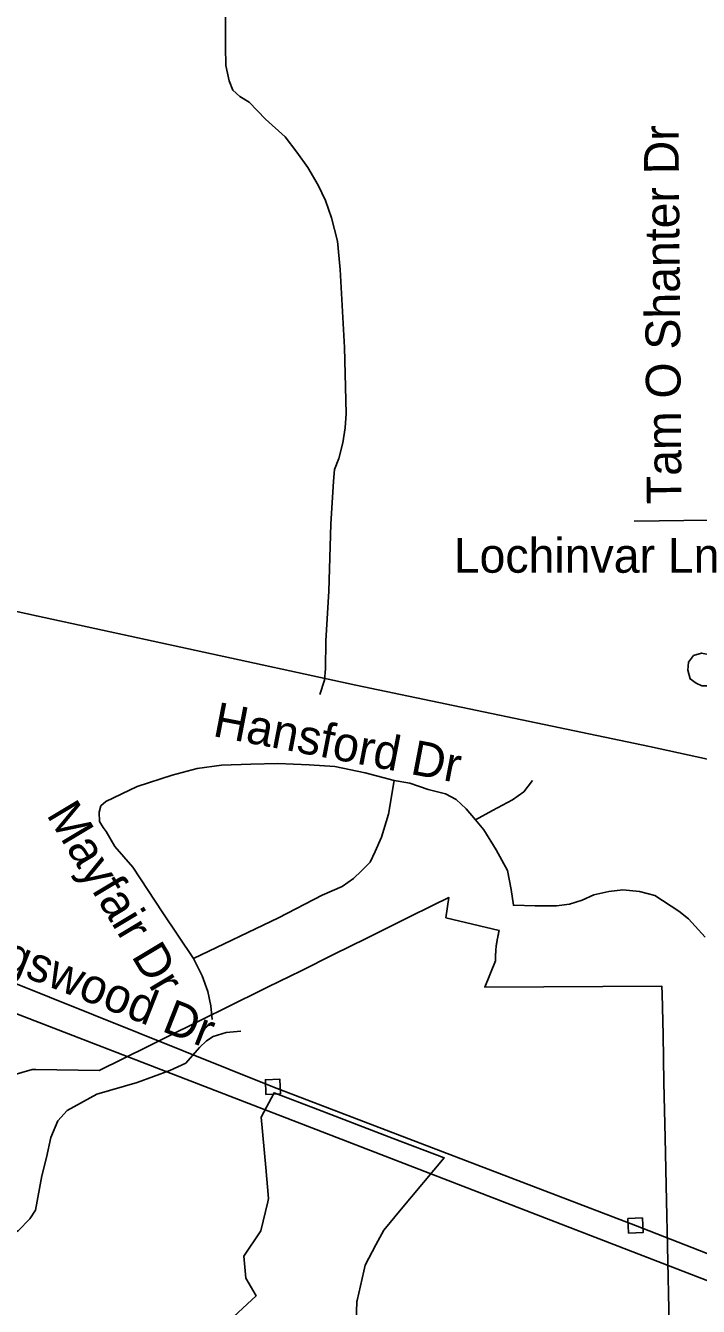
# Model space of a CAD drawing. Extents: x 2220236 to 2384410, y 720751 to 894131.
# Drawn here: x 2335051 to 2336892, y 803431 to 806939 of the extents above; entities that cross this region are included whole.
import ezdxf

# ---------------------------------------------------------------- set-up
doc = ezdxf.new("R2010")
doc.units = 0
doc.layers.add('Default', color=7, linetype='Continuous')

msp = doc.modelspace()

# ---------------------------------------------------------------- linework, layer by layer
at = {"layer": 'Default'}
msp.add_line((2336920.7, 805583.9), (2336716.9, 805581.6), dxfattribs=at)
for points in [[(2335855.8, 805106.3), (2335868.9, 805145.6), (2335871.5, 805177.1), (2335872.8, 805253.2), (2335880.7, 805389.6), (2335885.9, 805573.2), (2335893.8, 805691.2), (2335896.4, 805722.7), (2335908.2, 805752.8), (2335918.7, 805796.1), (2335925.2, 805836.8), (2335927.9, 805876.1), (2335925.2, 805985), (2335923.9, 806057.1), (2335912.1, 806270.9), (2335904.3, 806348.2), (2335888.5, 806412.5), (2335871.5, 806459.7), (2335851.8, 806501.7), (2335823, 806550.2), (2335792.9, 806592.2), (2335761.4, 806634.1), (2335707.7, 806682.6), (2335663.1, 806728.5), (2335636.9, 806744.3), (2335618.5, 806761.3), (2335608.1, 806787.6), (2335598.9, 806829.5), (2335597.6, 806880.7), (2335597.6, 806973.8)], [(2331380.2, 806148.5), (2332089.7, 805986.2), (2332785.1, 805833.7), (2333023.7, 805785.1), (2333486.9, 805676.6), (2334090.2, 805538), (2335080.6, 805321.9), (2335954.5, 805132.5), (2336758.3, 804964.2), (2337494, 804803.2), (2338191.7, 804647.6), (2339171.9, 804437.5), (2339987.8, 804257.3), (2340853.6, 804069.8), (2341802, 803859.4), (2342517.6, 803703.9), (2343209.2, 803550.3), (2344249.4, 803324.9), (2344734.6, 803222.8), (2345460.4, 803059.6)], [(2345020.4, 803226.3), (2344378.1, 802602.8), (2343567.7, 801835.2), (2342903.1, 801229.4), (2341981, 801590.2), (2340880.4, 802014.8), (2339974.4, 802379.8), (2338913.6, 802794.9), (2336720, 803652.3), (2335727.9, 804032.2), (2334504.4, 804523.2), (2333596.3, 804882.3), (2333041.1, 805671.2), (2333024.7, 805701.1)], [(2345128.8, 803203.5), (2344288.5, 802405.7), (2343608.3, 801777.6), (2342914.2, 801143.7), (2342458.1, 801324.1), (2341142.3, 801844), (2339390.6, 802528.8), (2337235.2, 803378.6), (2335128.1, 804193), (2333939.1, 804652.4), (2333547.2, 804811.7), (2333272.3, 805222.2), (2333026.4, 805555.2)], [(2336953.7, 805174.5), (2336951.5, 805198.6), (2336929.2, 805214.3), (2336901.2, 805219.9), (2336879.2, 805213.6), (2336865.6, 805195.5), (2336863.7, 805173.4), (2336870, 805149.4), (2336886.1, 805137.7), (2336902.2, 805130), (2336920.2, 805130.1), (2336944.1, 805144.5), (2336951.9, 805162.6), (2336953.7, 805174.5)], [(2335510.2, 804383.9), (2335426.4, 804508.8), (2335344.3, 804633.7), (2335294.7, 804690.2), (2335271, 804731.8), (2335263.4, 804742.2), (2335252.8, 804758.8), (2335251.9, 804784.4), (2335257.1, 804801.5), (2335270.7, 804813.4), (2335356.3, 804854.5), (2335452.1, 804885.3), (2335520.5, 804904.2), (2335587.2, 804912.7), (2335667.6, 804916.1), (2335741.1, 804917.9), (2335826.6, 804914.4), (2335896.8, 804909.3), (2335980.6, 804892.2), (2336060.1, 804870.8)], [(2336060.1, 804870.8), (2336043.9, 804779.2), (2336025, 804715.9), (2336007.9, 804676.5), (2335994.3, 804647.4), (2335970.3, 804623.5), (2335948.1, 804602.9), (2335917.3, 804580.7), (2335862.6, 804556.7), (2335742.8, 804495.1), (2335510.2, 804383.9)], [(2336282.5, 804763), (2336256.8, 804793.8), (2336229.4, 804819.4), (2336200.4, 804834.8), (2336152.5, 804846.8), (2336102.9, 804863.9), (2336060.1, 804870.8)], [(2336438.1, 804870.8), (2336414.2, 804840), (2336383.4, 804817.7), (2336328.6, 804788.6), (2336282.5, 804763)], [(2336911.1, 804442), (2336865.2, 804491.9), (2336838.9, 804513.6), (2336773.4, 804555.9), (2336731.5, 804567), (2336685.3, 804572.1), (2336647.6, 804567), (2336606.6, 804558.4), (2336574.1, 804543), (2336539.9, 804532.8), (2336504, 804527.6), (2336445.8, 804527.6), (2336385.9, 804529.3), (2336380, 804573), (2336369.7, 804624.3), (2336338.9, 804680.8), (2336304.7, 804735.6), (2336282.5, 804763)], [(2336812.8, 803379.9), (2336808, 803595.4), (2336805.2, 803719.9), (2336801.5, 803892.2), (2336798.2, 804043.9), (2336795.5, 804174.9), (2336793, 804286.9), (2336792.5, 804307.4), (2336307.5, 804305.2), (2336336.8, 804376.9), (2336336.8, 804382.4), (2336336.8, 804384.2), (2336336.8, 804387.9), (2336337, 804389.8), (2336337, 804393.6), (2336337.2, 804395.4), (2336337.2, 804397.2), (2336337.5, 804399.1), (2336337.5, 804400.9), (2336337.8, 804402.8), (2336337.8, 804404.7), (2336338, 804406.5), (2336338.2, 804408.4), (2336338.2, 804410.2), (2336338.8, 804413.9), (2336339, 804415.8), (2336339.2, 804417.6), (2336339.2, 804419.4), (2336339.5, 804421.3), (2336339.8, 804423.1), (2336340, 804425), (2336340.5, 804426.8), (2336340.8, 804428.6), (2336341, 804430.5), (2336341.2, 804432.3), (2336341.5, 804434.2), (2336341.8, 804436), (2336342.2, 804437.8), (2336342.5, 804439.6), (2336343, 804441.5), (2336343.2, 804443.3), (2336343.5, 804445.1), (2336344, 804446.9), (2336344.2, 804448.8), (2336344.8, 804450.6), (2336345.2, 804452.4), (2336345.5, 804454.2), (2336346, 804456), (2336346.5, 804457.8), (2336347.2, 804460.5), (2336201.2, 804495.2), (2336209.5, 804550.6), (2336166.5, 804529.3), (2336096.5, 804494.6), (2335985.2, 804439.6), (2335894, 804394.4), (2335804.8, 804350.2), (2335714.8, 804305.6), (2335593.2, 804245.5), (2335545.5, 804222), (2335289.5, 804095.2), (2335279.8, 804090.4), (2335252.5, 804076.9), (2335079.2, 804079.5), (2335069, 804079.9), (2333701.8, 803683)], [(2336812.8, 803379.9), (2336808, 803595.4), (2336805.2, 803719.9), (2336801.5, 803892.2), (2336798.2, 804043.9), (2336795.5, 804174.9), (2336793, 804286.9), (2336792.5, 804307.4), (2336307.5, 804305.2), (2336336.8, 804376.9), (2336336.8, 804382.4), (2336336.8, 804384.2), (2336336.8, 804387.9), (2336337, 804389.8), (2336337, 804393.6), (2336337.2, 804395.4), (2336337.2, 804397.2), (2336337.5, 804399.1), (2336337.5, 804400.9), (2336337.8, 804402.8), (2336337.8, 804404.7), (2336338, 804406.5), (2336338.2, 804408.4), (2336338.2, 804410.2), (2336338.8, 804413.9), (2336339, 804415.8), (2336339.2, 804417.6), (2336339.2, 804419.4), (2336339.5, 804421.3), (2336339.8, 804423.1), (2336340, 804425), (2336340.5, 804426.8), (2336340.8, 804428.6), (2336341, 804430.5), (2336341.2, 804432.3), (2336341.5, 804434.2), (2336341.8, 804436), (2336342.2, 804437.8), (2336342.5, 804439.6), (2336343, 804441.5), (2336343.2, 804443.3), (2336343.5, 804445.1), (2336344, 804446.9), (2336344.2, 804448.8), (2336344.8, 804450.6), (2336345.2, 804452.4), (2336345.5, 804454.2), (2336346, 804456), (2336346.5, 804457.8), (2336347.2, 804460.5), (2336201.2, 804495.2), (2336209.5, 804550.6), (2336166.5, 804529.3), (2336096.5, 804494.6), (2335985.2, 804439.6), (2335894, 804394.4), (2335804.8, 804350.2), (2335714.8, 804305.6), (2335593.2, 804245.5), (2335545.5, 804222), (2335289.5, 804095.2), (2335279.8, 804090.4), (2335252.5, 804076.9), (2335079.2, 804079.5), (2335069, 804079.9), (2333701.8, 803683)], [(2335510.2, 804383.9), (2335534.2, 804335.9), (2335549.5, 804293.1), (2335558.1, 804253.8), (2335561.5, 804216.1)], [(2335640.1, 804185), (2335600, 804180.6), (2335564.2, 804170.1), (2335546.3, 804158), (2335526.7, 804139.8), (2335489.2, 804097.3), (2335445.4, 804076.9), (2335355.9, 804043.8), (2335246.1, 804012.3), (2335164.7, 803967.4), (2335139.1, 803939.1), (2335119.7, 803892.9), (2335108.4, 803838.8), (2335095, 803788.6), (2335078, 803694.5), (2335062.4, 803670.3), (2335030.7, 803638), (2334963.2, 803605.2), (2334907.8, 803566.5), (2334723.6, 803416.3), (2334654.2, 803361.5)], [(2335708.8, 804011.4), (2335748.7, 804013), (2335747.1, 804053), (2335707.1, 804051.3), (2335708.8, 804011.4)], [(2335595, 803379.1), (2335681.5, 803460.1), (2335653.2, 803508.5), (2335648, 803568.6), (2335694.5, 803638), (2335713.5, 803717.5), (2335715.5, 803726.2), (2335708, 803811), (2335696, 803948.8), (2335730.8, 804015.7), (2335850.5, 803969.9), (2336056.8, 803891), (2336196.8, 803837.4), (2336079, 803696.9), (2336031.2, 803640), (2336009.8, 803599.4), (2335980.2, 803543.4), (2335976.5, 803526.9), (2335958, 803447.1), (2335957.5, 803444), (2335956, 803387.6)], [(2335595, 803379.1), (2335681.5, 803460.1), (2335653.2, 803508.5), (2335648, 803568.6), (2335694.5, 803638), (2335713.5, 803717.5), (2335715.5, 803726.2), (2335708, 803811), (2335696, 803948.8), (2335730.8, 804015.7), (2335850.5, 803969.9), (2336056.8, 803891), (2336196.8, 803837.4), (2336079, 803696.9), (2336031.2, 803640), (2336009.8, 803599.4), (2335980.2, 803543.4), (2335976.5, 803526.9), (2335958, 803447.1), (2335957.5, 803444), (2335956, 803387.6)], [(2336700.9, 803631.5), (2336740.8, 803633.1), (2336739.2, 803673.1), (2336699.3, 803671.5), (2336700.9, 803631.5)]]:
    msp.add_lwpolyline(points, dxfattribs=at)

# ---------------------------------------------------------------- texts
for s, rotation, p in [('Tam O Shanter Dr', 90.4656, (2336846.3, 805628.2)), ('Hansford Dr', 349.1385, (2335560.3, 804993.2)), ('Mayfair Dr', 300.962, (2335106.4, 804777.8)), ('Kingswood Dr', 338.5015, (2334809.4, 804426.5))]:
    msp.add_text(s, height=95, rotation=rotation, dxfattribs=at).set_placement(p)
msp.add_text('Lochinvar Ln', height=95, dxfattribs=at).set_placement((2336222.7, 805440.1))

doc.saveas('drawing.dxf')
